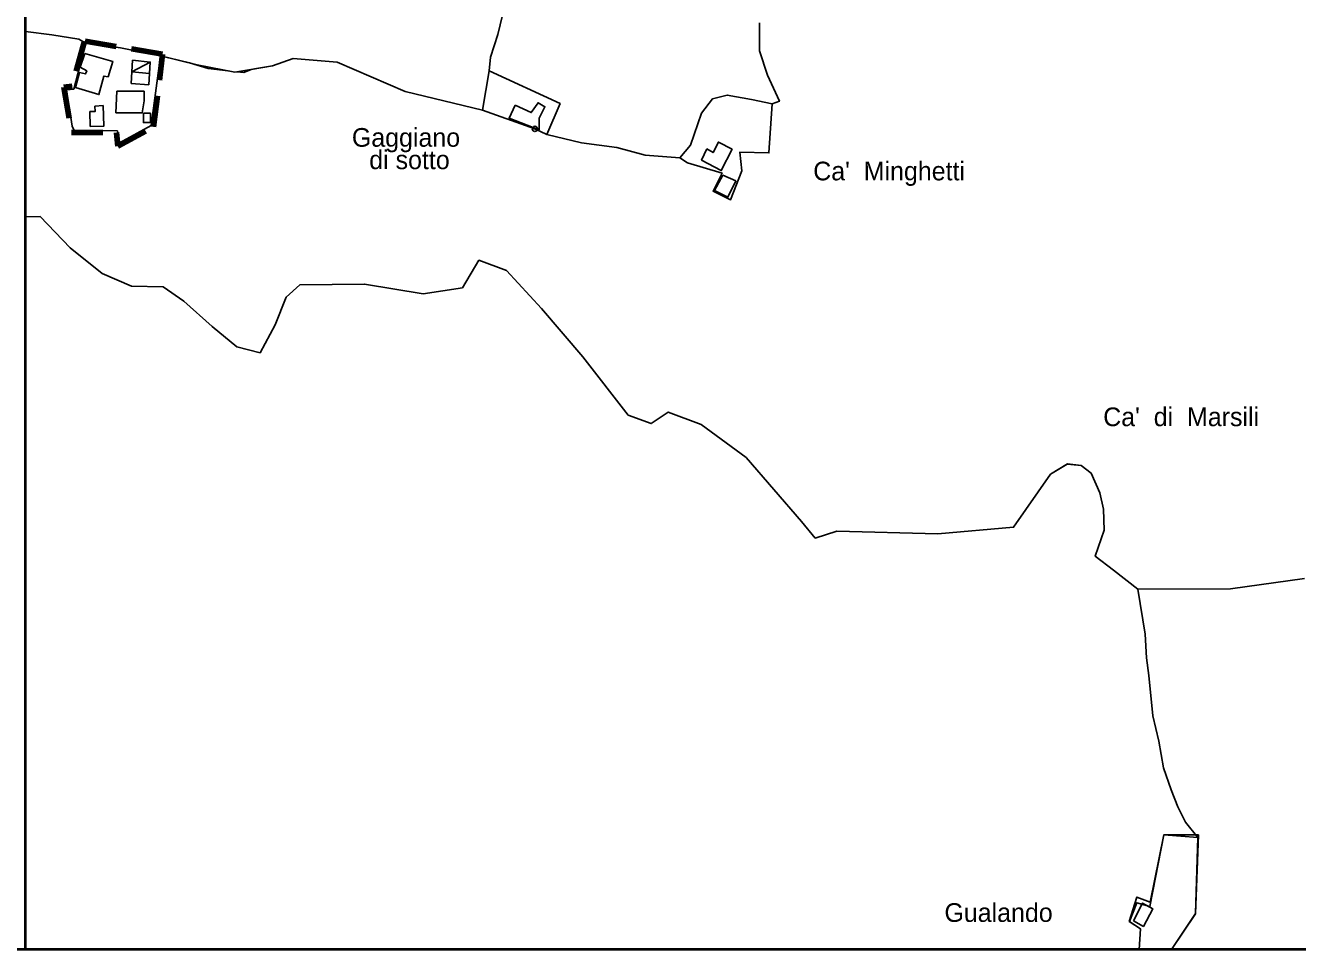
# Model space of a CAD drawing. Extents: x 652791 to 656927, y 889884 to 892405.
# Drawn here: x 654894 to 655576, y 889884 to 890379 of the extents above; entities that cross this region are included whole.
import ezdxf
from ezdxf.enums import TextEntityAlignment as Align

# ---------------------------------------------------------------- set-up
doc = ezdxf.new("R2010")
doc.units = 0
doc.header["$LTSCALE"] = 5.6
doc.header["$PDMODE"] = 32
doc.header["$PDSIZE"] = 2.8
doc.linetypes.add('MEDIUM_DASHED', pattern=[4.5, 3, -1.5])
for name, color, linetype, lineweight in [('1', 7, 'Continuous', 25), ('2', 7, 'Continuous', 25), ('3', 7, 'Continuous', 25), ('36', 7, 'Continuous', 25), ('37', 7, 'Continuous', 25), ('4', 7, 'Continuous', 25), ('6', 7, 'Continuous', 25), ('61', 7, 'Continuous', 35), ('7', 7, 'MEDIUM_DASHED', 100)]:
    doc.layers.add(name, color=color, linetype=linetype, lineweight=lineweight)
doc.layers.add('60', color=7, linetype='Continuous')

msp = doc.modelspace()

# ---------------------------------------------------------------- linework, layer by layer
at = {"layer": '1'}
msp.add_line((654951.08, 890354.43), (654960.92, 890359.61), dxfattribs=at)
for points in [[(654926.43, 890369.77), (654919.88, 890345.22), (654916.07, 890344.79)], [(654966.42, 890363), (654945.05, 890367.23), (654926.43, 890369.77)], [(654916.07, 890344.79), (654919.14, 890325.39), (654920.09, 890322.99), (654943.36, 890322.78), (654944.42, 890316.43), (654961.34, 890325.74), (654966.42, 890363)]]:
    msp.add_lwpolyline(points, dxfattribs=at)
for points in [[(654925.8, 890364.27), (654923.4, 890356.93), (654926.86, 890354.96), (654926.27, 890353.29), (654922.97, 890353.99), (654920.81, 890345.95), (654933.42, 890342.25), (654936.1, 890352.19), (654938.32, 890351.76), (654940.82, 890360.04)], [(654951.4, 890360.67), (654951.08, 890354.43), (654960.5, 890353.58), (654960.92, 890359.61)], [(654951.08, 890354.43), (654950.76, 890348.18), (654960.07, 890347.55), (654960.5, 890353.58)], [(654943.06, 890344.15), (654942.49, 890332.52), (654956.55, 890332.46), (654957.71, 890338.95), (654957.63, 890344)], [(654931.3, 890336.11), (654931.37, 890333.16), (654928.62, 890333.15), (654928.78, 890325.19), (654936.06, 890325.4), (654935.67, 890336.31)]]:
    msp.add_lwpolyline(points, close=True, dxfattribs=at)
at = {"layer": '2'}
for points in [[(655256.33, 890332.35), (655262.12, 890339.95), (655270.08, 890341.94), (655283.11, 890339.59), (655294.14, 890337.23), (655292.36, 890310.97), (655276.87, 890311.47), (655277.87, 890301.47), (655271.88, 890285.97), (655262.52, 890290.57), (655267.33, 890300.21)], [(655267.33, 890300.21), (655248.74, 890305.75), (655244.71, 890308.44), (655250.36, 890315.15), (655256.33, 890332.35)]]:
    msp.add_lwpolyline(points, dxfattribs=at)
for points in [[(655259.05, 890313.16), (655256.33, 890307.19), (655266.83, 890301.57), (655272.62, 890312.98), (655265.38, 890316.78), (655262.49, 890311.17)], [(655267.67, 890299.15), (655274.66, 890296.03), (655270.43, 890287.31), (655263.26, 890290.82)]]:
    msp.add_lwpolyline(points, close=True, dxfattribs=at)
at = {"layer": '3'}
for points in [[(655138.98, 890333.95), (655167, 890323.87), (655173.49, 890320.87), (655180.49, 890337.38), (655142.59, 890355)], [(655156.39, 890336.57), (655153.18, 890329.55), (655169.29, 890323.35), (655169.36, 890329.61), (655172.41, 890335.75), (655168.7, 890337.88), (655165.03, 890332.6)]]:
    msp.add_lwpolyline(points, close=True, dxfattribs=at)
at = {"layer": '36'}
for points in [[(655173.64, 890479.1), (655163.35, 890470.47), (655152.23, 890456.28), (655134.36, 890428.2), (655127.86, 890405.96), (655142.79, 890395.56), (655150.78, 890389.16), (655147.19, 890374.49), (655143.19, 890362.36)], [(655191.94, 890316.47), (655210.91, 890313.84), (655226.17, 890309.83), (655244.71, 890308.44), (655250.36, 890315.15), (655256.33, 890332.35), (655262.12, 890339.95), (655270.08, 890341.94), (655283.11, 890339.59), (655294.14, 890337.23), (655298.01, 890338.65), (655291.63, 890352.64), (655287.44, 890365.64), (655287.37, 890380.6)], [(655143.19, 890362.36), (655142.59, 890355), (655180.49, 890337.38), (655173.49, 890320.87), (655191.94, 890316.47)], [(655490.75, 889884.41), (654894.04, 889884.41), (654894.04, 890276.86), (654901.98, 890276.95), (654918.07, 890260.12), (654935.21, 890246.4), (654950.95, 890239.62), (654967.84, 890239.25), (654978.94, 890231.7), (654994.1, 890218.12)], [(654994.1, 890218.12), (655007.32, 890207.24), (655019.75, 890203.98), (655027.9, 890218.93), (655033.69, 890233.8), (655041.04, 890240.28), (655075.73, 890240.75), (655107.21, 890235.49), (655128.14, 890238.81), (655136.97, 890253.53), (655151.85, 890248.12), (655170.51, 890227.75), (655192.67, 890201.73), (655217.01, 890170.49), (655229.36, 890166.07), (655238.48, 890172.26), (655256.14, 890165.49), (655280.16, 890147.89), (655309.88, 890113.68), (655317.24, 890104.73), (655328.81, 890108.42), (655382.98, 890107.1), (655423.49, 890110.54), (655443.22, 890138.95), (655452.42, 890144.47)], [(655452.42, 890144.47), (655459.76, 890143.7), (655465.06, 890139.58), (655469.77, 890128.97)], [(655469.77, 890128.97), (655471.67, 890120.17), (655471.96, 890108.98), (655467.12, 890095.11), (655477.1, 890087.65), (655490.07, 890077.44)], [(655522.14, 889944.49), (655515.6, 889952.67), (655511.51, 889960.85), (655507.84, 889969.85), (655503.75, 889981.71), (655501.3, 889996.02), (655498.03, 890009.52), (655495.98, 890031.19), (655494.76, 890040.6), (655493.94, 890053.28), (655490.07, 890077.44), (655539.7, 890077.52), (655579.35, 890083.18)], [(655490.07, 890077.44), (655493.94, 890053.28), (655494.76, 890040.6), (655495.98, 890031.19), (655498.03, 890009.52), (655501.3, 889996.02), (655503.75, 889981.71), (655507.84, 889969.85), (655511.51, 889960.85), (655515.6, 889952.67), (655522.14, 889944.49), (655504.08, 889945.84), (655496.54, 889907.5), (655489.54, 889909.5), (655485.54, 889899.49), (655491.54, 889895.49), (655490.75, 889884.41)], [(655827.32, 889884.41), (655508.15, 889884.41), (655520.95, 889903.63), (655522.14, 889944.49)]]:
    msp.add_lwpolyline(points, dxfattribs=at)
at = {"layer": '37'}
for p, q in [((654894.04, 890443.41), (654894.04, 890376)), ((655167, 890323.87), (655138.98, 890333.95))]:
    msp.add_line(p, q, dxfattribs=at)
for points in [[(655061.02, 890359.53), (655097.56, 890343.86), (655138.98, 890333.95), (655142.59, 890355), (655143.19, 890362.36), (655147.19, 890374.49), (655150.78, 890389.16), (655142.79, 890395.56), (655127.86, 890405.96), (655134.36, 890428.2), (655152.23, 890456.28)], [(655287.37, 890380.6), (655287.44, 890365.64), (655291.63, 890352.64), (655298.01, 890338.65), (655294.14, 890337.23), (655292.36, 890310.97), (655276.87, 890311.47), (655277.87, 890301.47), (655271.88, 890285.97), (655262.52, 890290.57), (655267.33, 890300.21), (655248.74, 890305.75), (655244.71, 890308.44), (655226.17, 890309.83), (655210.91, 890313.84), (655191.94, 890316.47), (655173.49, 890320.87), (655167, 890323.87)], [(654894.04, 890376), (654908.19, 890374.3), (654922.62, 890371.9)], [(654922.62, 890371.9), (654908.19, 890374.3), (654894.04, 890376), (654894.04, 890276.86)], [(654920.09, 890322.99), (654919.14, 890325.39), (654916.07, 890344.79), (654919.88, 890345.22), (654926.43, 890369.77), (654922.62, 890371.9)], [(654922.62, 890371.9), (654926.43, 890369.77), (654945.05, 890367.23), (654966.42, 890363), (654981.9, 890359.22)], [(654966.42, 890363), (654961.34, 890325.74), (654944.42, 890316.43), (654943.36, 890322.78), (654920.09, 890322.99)], [(655138.98, 890333.95), (655097.56, 890343.86), (655061.02, 890359.53), (655037.53, 890361.48), (655026.44, 890357.57), (655006.21, 890354.3), (654985.99, 890358.22), (654966.42, 890363)], [(654981.9, 890359.22), (654991.96, 890356.13), (655002.58, 890355.01)], [(655007.42, 890354.5), (655011.13, 890354.11), (655014.91, 890355.71), (655026.44, 890357.57)], [(655026.44, 890357.57), (655037.53, 890361.48), (655061.02, 890359.53)], [(655002.58, 890355.01), (655006.21, 890354.3), (655007.42, 890354.5)], [(654894.04, 890276.86), (654901.98, 890276.95), (654918.07, 890260.12), (654927.87, 890252.27), (654935.21, 890246.4)], [(654994.1, 890218.12), (655007.32, 890207.24), (655019.75, 890203.98), (655027.9, 890218.93), (655033.69, 890233.8), (655041.04, 890240.28), (655075.73, 890240.75), (655107.21, 890235.49), (655128.14, 890238.81), (655136.97, 890253.53), (655151.85, 890248.12), (655170.51, 890227.75), (655192.67, 890201.73), (655217.01, 890170.49), (655229.36, 890166.07), (655238.48, 890172.26), (655256.14, 890165.49), (655280.16, 890147.89), (655309.88, 890113.68), (655317.24, 890104.73), (655328.81, 890108.42), (655382.98, 890107.1), (655423.49, 890110.54), (655443.22, 890138.95), (655452.12, 890144.28)], [(654935.21, 890246.4), (654950.95, 890239.62), (654967.84, 890239.25), (654978.94, 890231.7), (654994.1, 890218.12)], [(655452.12, 890144.28), (655459.76, 890143.7), (655465.06, 890139.58), (655469.77, 890128.97)], [(655469.77, 890128.97), (655471.67, 890120.17), (655471.96, 890108.98), (655467.12, 890095.11), (655477.1, 890087.65), (655490.07, 890077.44), (655539.7, 890077.52), (655579.35, 890083.18)]]:
    msp.add_lwpolyline(points, dxfattribs=at)
msp.add_point((655167, 890323.87), dxfattribs=at)
at = {"layer": '4'}
for points in [[(655522.6, 889945.81), (655504.05, 889945.81), (655496.69, 889909.73), (655489.45, 889912.54), (655485.48, 889899.51), (655491.48, 889895.51), (655490.72, 889884.41)], [(655490.72, 889884.41), (655508.14, 889884.41), (655520.92, 889903.6), (655522.6, 889945.81)]]:
    msp.add_lwpolyline(points, dxfattribs=at)
msp.add_lwpolyline([(655487.74, 889899.77), (655492.6, 889909.26), (655498.02, 889906.27), (655493.04, 889896.75)], close=True, dxfattribs=at)
at = {"layer": '6'}
msp.add_lwpolyline([(654957.23, 890332.25), (654960.98, 890332.25), (654960.98, 890327.25), (654957.23, 890327.25)], close=True, dxfattribs=at)
at = {"layer": '61', "lineweight": 40}
msp.add_line((654894.04, 889884.41), (652791.02, 889884.41), dxfattribs=at)
msp.add_lwpolyline([(654894.04, 892404.68), (656926.84, 892404.68), (656926.84, 889884.41), (654894.04, 889884.41)], close=True, dxfattribs=at)
at = {"layer": '7'}
msp.add_lwpolyline([(654925.72, 890370.89), (654919.03, 890346.71), (654914.66, 890346.2), (654918.65, 890322.02), (654942.81, 890321.9), (654943.58, 890314.57), (654962.73, 890324.98), (654967.49, 890363.95)], close=True, dxfattribs=at)

# ---------------------------------------------------------------- texts
at = {"layer": '60'}
for s, p in [('Gaggiano ', (655099.8, 890314.31)), ('di sotto', (655099.8, 890302.31)), ("Ca'  Minghetti", (655356.8, 890296.31)), ("Ca'  di  Marsili", (655513.28, 890164.68)), ('Gualando', (655415.44, 889899.22))]:
    msp.add_text(s, height=10, dxfattribs=at).set_placement(p, align=Align.CENTER)

doc.saveas('drawing.dxf')
